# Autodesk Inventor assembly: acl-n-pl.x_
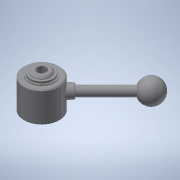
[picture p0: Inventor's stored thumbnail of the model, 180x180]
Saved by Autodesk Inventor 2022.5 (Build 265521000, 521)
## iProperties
Part Number: acl-n-pl.x_
Material: 一般
Document SubType Name: Assembly
Designer: ImaoCorp
Sending System: SOLIDWORKS 2017-2017317
MC: AMD64
MC_MODEL: Intel64 Family 6 Model 60 Stepping 3, GenuineIntel
OS: Windows_NT
FRU: Parasolid Version 29.0, build 201,  4-17-2017
FORMAT: text
GUISE: transmit
KEY: acl-n-pl
FILE: acl-n-pl.x_t
DATE: Tue Jun 18 13:07:33 2019
Author: ImaoCorp
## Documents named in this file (4)
- X:\14_SW2022-Inv2022\00_全2023-1023新製品(TCC)まで\a\acl-n-pl\ACL-N-PL.iam
- X:\14_SW2022-Inv2022\00_全2023-1023新製品(TCC)まで\a\acl-n-pl\acl-n-pl_01.ipt
- X:\14_SW2022-Inv2022\00_全2023-1023新製品(TCC)まで\a\acl-n-pl\acl-n-pl_02.ipt
- X:\14_SW2022-Inv2022\00_全2023-1023新製品(TCC)まで\a\acl-n-pl\acl-n-pl_03.ipt
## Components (3 placed, 3 different names)
1. acl-n-pl_01
2. acl-n-pl_02
3. acl-n-pl_03
